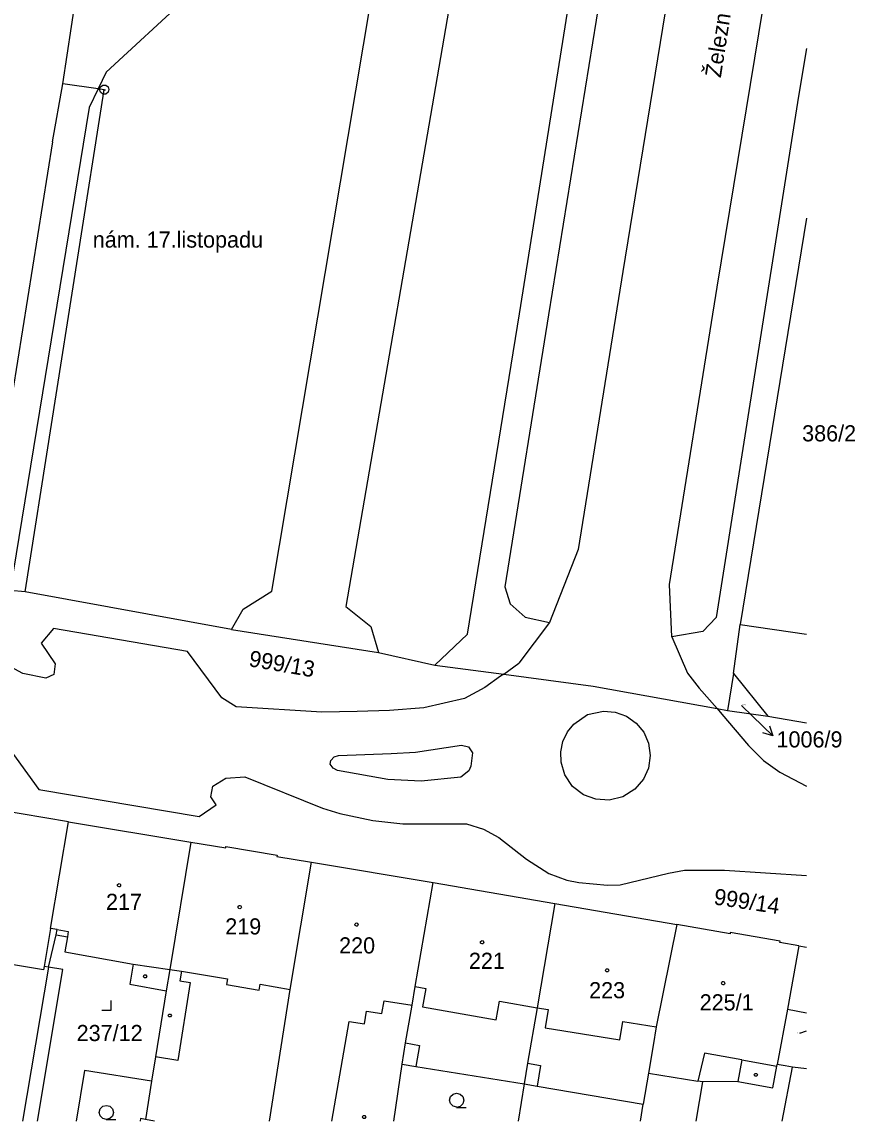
# Model space of a CAD drawing. Extents: x -851495 to -851222, y -1010479 to -1010202.
# Drawn here: x -851310.2 to -851222.4, y -1010478.7 to -1010362.9 of the extents above; entities that cross this region are included whole.
import ezdxf

# ---------------------------------------------------------------- set-up
doc = ezdxf.new("R2010")
doc.units = 0
for name, color, linetype in [('1', 7, 'Continuous'), ('12', 7, 'Continuous'), ('2', 7, 'Continuous'), ('3', 7, 'Continuous'), ('4', 7, 'Continuous'), ('5', 7, 'Continuous'), ('7', 7, 'Continuous'), ('8', 7, 'Continuous')]:
    doc.layers.add(name, color=color, linetype=linetype)

# ---------------------------------------------------------------- blocks, each defined once
blk = doc.blocks.new('304')
blk.add_lwpolyline([(0, 0), (-0.38, 0.1), (-0.65, 0.37), (-0.75, 0.74), (-0.65, 1.11), (-0.38, 1.38), (-0.01, 1.48), (0.36, 1.38), (0.63, 1.11), (0.73, 0.73), (0.63, 0.35), (0.36, 0.08), (-0.02, -0.02), (0.98, -0.02)])
blk = doc.blocks.new('319')
blk.add_lwpolyline([(-0.5, 0), (0.5, 0), (0.5, 1)])
blk = doc.blocks.new('10292')
blk.add_line((0, 3), (0, 0))
blk.add_lwpolyline([(-0.5, 2), (0, 3), (0.5, 2)])
blk = doc.blocks.new('402')
blk.add_lwpolyline([(0.09, 0.15), (0.18, 0), (0.09, -0.15), (-0.09, -0.15), (-0.18, 0), (-0.09, 0.15), (0.09, 0.15)])
blk = doc.blocks.new('105')
blk.add_line((-0.12, 0), (0.12, 0))
blk.add_lwpolyline([(0.15, 0.48), (0.4, 0.3), (0.5, 0.01), (0.4, -0.28), (0.15, -0.46), (-0.16, -0.46), (-0.41, -0.28), (-0.51, 0.01), (-0.41, 0.3), (-0.16, 0.48), (0.15, 0.48)])
blk = doc.blocks.new('404')
blk.add_lwpolyline([(0, 0.17), (0.1, 0.15), (0.15, 0.06), (0.17, 0), (0.15, -0.09), (0.07, -0.16), (0, -0.17), (-0.09, -0.14), (-0.15, -0.08), (-0.17, 0), (-0.15, 0.09), (-0.07, 0.16), (0, 0.17)])

msp = doc.modelspace()

# ---------------------------------------------------------------- linework, layer by layer
at = {"layer": '1'}
for p, q in [((-851305.87, -1010369.39), (-851303.96, -1010356.63)), ((-851242.07, -1010359.77), (-851246.84, -1010389.17)), ((-851302.16, -1010369.92), (-851305.87, -1010369.39)), ((-851301.51, -1010370.01), (-851302.16, -1010369.92)), ((-851309.84, -1010422.92), (-851301.51, -1010370.01)), ((-851227.5, -1010383.55), (-851234.48, -1010426.35)), ((-851246.84, -1010389.17), (-851251.57, -1010418.46)), ((-851251.57, -1010418.46), (-851254.57, -1010426.15)), ((-851309.84, -1010422.92), (-851311.44, -1010422.76)), ((-851288.09, -1010426.86), (-851309.84, -1010422.92)), ((-851254.57, -1010426.15), (-851257.83, -1010430.41)), ((-851235.2, -1010431.5), (-851234.48, -1010426.35)), ((-851234.48, -1010426.35), (-851227.5, -1010427.36)), ((-851306.87, -1010426.78), (-851308.15, -1010428.31)), ((-851292.74, -1010429.19), (-851306.87, -1010426.78)), ((-851288.09, -1010426.86), (-851272.59, -1010429.29)), ((-851308.15, -1010428.31), (-851306.7, -1010430.49)), ((-851289.12, -1010434.09), (-851292.74, -1010429.19)), ((-851272.59, -1010429.29), (-851266.67, -1010430.62)), ((-851310.1, -1010431.5), (-851312.57, -1010430.18)), ((-851306.7, -1010430.49), (-851306.81, -1010431.62)), ((-851266.67, -1010430.62), (-851259.39, -1010431.59)), ((-851259.39, -1010431.59), (-851257.83, -1010430.41)), ((-851307.65, -1010432), (-851310.1, -1010431.5)), ((-851306.81, -1010431.62), (-851307.65, -1010432)), ((-851259.76, -1010431.8), (-851261.39, -1010432.98)), ((-851259.39, -1010431.59), (-851259.76, -1010431.8)), ((-851259.39, -1010431.59), (-851249.99, -1010432.85)), ((-851235.2, -1010431.5), (-851235.84, -1010435.39)), ((-851235.2, -1010431.5), (-851231.57, -1010436.01)), ((-851261.39, -1010432.98), (-851263.56, -1010434.13)), ((-851249.99, -1010432.85), (-851236.92, -1010435.2)), ((-851287.62, -1010435.01), (-851289.12, -1010434.09)), ((-851263.56, -1010434.13), (-851267.84, -1010435.13)), ((-851278.59, -1010435.57), (-851287.62, -1010435.01)), ((-851274.84, -1010435.52), (-851278.59, -1010435.57)), ((-851271.44, -1010435.4), (-851274.84, -1010435.52)), ((-851267.84, -1010435.13), (-851271.44, -1010435.4)), ((-851236.92, -1010435.2), (-851235.84, -1010435.39)), ((-851236.92, -1010435.2), (-851236.41, -1010435.78)), ((-851236.41, -1010435.78), (-851233.63, -1010439.08)), ((-851235.84, -1010435.39), (-851231.57, -1010436.01)), ((-851231.57, -1010436.01), (-851227.5, -1010436.72)), ((-851311.97, -1010438.79), (-851308.42, -1010443.72)), ((-851233.63, -1010439.08), (-851232.04, -1010440.68)), ((-851232.04, -1010440.68), (-851230.3, -1010441.91)), ((-851290.08, -1010443.38), (-851288.68, -1010442.53)), ((-851288.68, -1010442.53), (-851286.71, -1010442.41)), ((-851286.71, -1010442.41), (-851278.51, -1010445.68)), ((-851230.3, -1010441.91), (-851227.5, -1010443.37)), ((-851308.42, -1010443.72), (-851291.49, -1010446.56)), ((-851290.26, -1010444.49), (-851290.08, -1010443.38)), ((-851289.7, -1010445.36), (-851290.26, -1010444.49)), ((-851305.28, -1010447.12), (-851316.57, -1010445.23)), ((-851291.49, -1010446.56), (-851289.7, -1010445.36)), ((-851278.51, -1010445.68), (-851276.67, -1010446.25)), ((-851276.67, -1010446.25), (-851273.21, -1010447)), ((-851307.18, -1010458.37), (-851305.28, -1010447.12)), ((-851305.28, -1010447.12), (-851292.38, -1010449.28)), ((-851273.21, -1010447), (-851270.04, -1010447.35)), ((-851270.04, -1010447.35), (-851263.33, -1010447.35)), ((-851263.33, -1010447.35), (-851261.53, -1010447.92)), ((-851261.53, -1010447.92), (-851259.94, -1010448.77)), ((-851292.38, -1010449.28), (-851294.6, -1010462.68)), ((-851292.38, -1010449.28), (-851288.71, -1010449.89)), ((-851288.71, -1010449.89), (-851288.69, -1010449.75)), ((-851288.69, -1010449.75), (-851283.29, -1010450.64)), ((-851259.94, -1010448.77), (-851257.01, -1010451.05)), ((-851283.29, -1010450.64), (-851283.31, -1010450.78)), ((-851283.31, -1010450.78), (-851279.68, -1010451.38)), ((-851281.9, -1010464.78), (-851279.68, -1010451.38)), ((-851279.68, -1010451.38), (-851266.85, -1010453.52)), ((-851257.01, -1010451.05), (-851254.65, -1010452.56)), ((-851254.65, -1010452.56), (-851252.75, -1010453.27)), ((-851252.75, -1010453.27), (-851251.49, -1010453.52)), ((-851247.15, -1010453.76), (-851242.06, -1010452.53)), ((-851242.06, -1010452.53), (-851240.35, -1010452.22)), ((-851240.35, -1010452.22), (-851236.13, -1010452.21)), ((-851236.13, -1010452.21), (-851227.5, -1010452.8)), ((-851268.73, -1010464.49), (-851266.85, -1010453.52)), ((-851266.85, -1010453.52), (-851254.03, -1010455.72)), ((-851251.49, -1010453.52), (-851248.46, -1010453.82)), ((-851248.46, -1010453.82), (-851247.15, -1010453.76)), ((-851254.03, -1010455.72), (-851255.89, -1010466.71)), ((-851254.03, -1010455.72), (-851241.18, -1010457.95)), ((-851307.4, -1010462.45), (-851306.56, -1010459.04)), ((-851306.46, -1010458.49), (-851307.18, -1010458.37)), ((-851306.56, -1010459.04), (-851306.46, -1010458.49)), ((-851306.46, -1010458.49), (-851305.3, -1010458.68)), ((-851305.3, -1010458.68), (-851305.4, -1010459.26)), ((-851241.18, -1010457.95), (-851243.34, -1010468.73)), ((-851235.56, -1010458.93), (-851241.18, -1010457.95)), ((-851235.53, -1010458.79), (-851235.56, -1010458.93)), ((-851230.28, -1010459.71), (-851235.53, -1010458.79)), ((-851305.4, -1010459.26), (-851305.65, -1010460.84)), ((-851230.31, -1010459.85), (-851230.28, -1010459.71)), ((-851228.3, -1010460.2), (-851230.31, -1010459.85)), ((-851228.3, -1010460.2), (-851229.52, -1010466.86)), ((-851228.3, -1010460.2), (-851227.5, -1010460.34)), ((-851307.9, -1010462.72), (-851318.74, -1010460.9)), ((-851305.65, -1010460.84), (-851298.47, -1010462.13)), ((-851307.84, -1010462.38), (-851307.9, -1010462.72)), ((-851307.4, -1010462.45), (-851307.84, -1010462.38)), ((-851305.89, -1010462.7), (-851307.4, -1010462.45)), ((-851298.47, -1010462.13), (-851298.83, -1010464.25)), ((-851308.54, -1010478.65), (-851305.89, -1010462.7)), ((-851294.6, -1010462.68), (-851294.99, -1010464.95)), ((-851298.83, -1010464.25), (-851294.99, -1010464.95)), ((-851284.09, -1010478.65), (-851281.9, -1010464.78)), ((-851269.07, -1010466.46), (-851268.73, -1010464.49)), ((-851294.99, -1010464.95), (-851296.11, -1010471.88)), ((-851269.75, -1010470.43), (-851269.07, -1010466.46)), ((-851255.89, -1010466.71), (-851256.92, -1010472.57)), ((-851229.52, -1010466.86), (-851230.6, -1010472.71)), ((-851229.52, -1010466.86), (-851227.5, -1010467.27)), ((-851243.34, -1010468.73), (-851243.67, -1010470.7)), ((-851270.13, -1010472.65), (-851269.75, -1010470.43)), ((-851243.67, -1010470.7), (-851244.16, -1010473.61)), ((-851296.11, -1010471.88), (-851296.53, -1010474.46)), ((-851271, -1010478.65), (-851270.13, -1010472.65)), ((-851270.13, -1010472.65), (-851268.67, -1010472.9)), ((-851268.67, -1010472.9), (-851257.27, -1010474.75)), ((-851256.92, -1010472.57), (-851257.27, -1010474.75)), ((-851231.06, -1010475.17), (-851230.63, -1010472.86)), ((-851230.63, -1010472.86), (-851230.6, -1010472.71)), ((-851229.75, -1010472.85), (-851230.6, -1010472.71)), ((-851230.05, -1010478.65), (-851228.97, -1010472.96)), ((-851228.97, -1010472.96), (-851229.75, -1010472.85)), ((-851227.5, -1010473.17), (-851228.97, -1010472.96)), ((-851303.59, -1010473.33), (-851304.48, -1010478.65)), ((-851296.53, -1010474.46), (-851303.59, -1010473.33)), ((-851244.16, -1010473.61), (-851244.71, -1010476.86)), ((-851244.16, -1010473.61), (-851238.94, -1010474.45)), ((-851296.53, -1010474.46), (-851297.18, -1010478.48)), ((-851257.27, -1010474.75), (-851257.87, -1010478.65)), ((-851257.27, -1010474.75), (-851255.87, -1010474.97)), ((-851255.87, -1010474.97), (-851244.71, -1010476.86)), ((-851238.45, -1010474.53), (-851239.15, -1010478.65)), ((-851238.45, -1010474.53), (-851238.94, -1010474.45)), ((-851234.73, -1010474.48), (-851238.45, -1010474.53)), ((-851234.73, -1010474.48), (-851231.06, -1010475.17)), ((-851245.01, -1010478.65), (-851244.71, -1010476.86)), ((-851297.68, -1010478.39), (-851297.73, -1010478.65)), ((-851297.18, -1010478.48), (-851297.68, -1010478.39)), ((-851296.23, -1010478.65), (-851297.18, -1010478.48))]:
    msp.add_line(p, q, dxfattribs=at)
at = {"layer": '12'}
for p, q in [((-851227.5, -1010383.55), (-851234.48, -1010426.35)), ((-851234.48, -1010426.35), (-851227.5, -1010427.36)), ((-851305.28, -1010447.12), (-851316.57, -1010445.23)), ((-851307.18, -1010458.37), (-851305.28, -1010447.12)), ((-851307.18, -1010458.37), (-851305.28, -1010447.12)), ((-851305.28, -1010447.12), (-851292.38, -1010449.28)), ((-851292.38, -1010449.28), (-851294.6, -1010462.68)), ((-851292.38, -1010449.28), (-851294.6, -1010462.68)), ((-851292.38, -1010449.28), (-851288.71, -1010449.89)), ((-851288.71, -1010449.89), (-851288.69, -1010449.75)), ((-851288.69, -1010449.75), (-851283.29, -1010450.64)), ((-851283.29, -1010450.64), (-851283.31, -1010450.78)), ((-851283.31, -1010450.78), (-851279.68, -1010451.38)), ((-851281.9, -1010464.78), (-851279.68, -1010451.38)), ((-851281.9, -1010464.78), (-851279.68, -1010451.38)), ((-851279.68, -1010451.38), (-851266.85, -1010453.52)), ((-851268.73, -1010464.49), (-851266.85, -1010453.52)), ((-851268.73, -1010464.49), (-851266.85, -1010453.52)), ((-851266.85, -1010453.52), (-851254.03, -1010455.72)), ((-851254.03, -1010455.72), (-851255.89, -1010466.71)), ((-851254.03, -1010455.72), (-851255.89, -1010466.71)), ((-851254.03, -1010455.72), (-851241.18, -1010457.95)), ((-851307.18, -1010458.37), (-851307.84, -1010462.38)), ((-851306.46, -1010458.49), (-851307.18, -1010458.37)), ((-851306.46, -1010458.49), (-851305.3, -1010458.68)), ((-851305.3, -1010458.68), (-851305.4, -1010459.26)), ((-851241.18, -1010457.95), (-851243.34, -1010468.73)), ((-851241.18, -1010457.95), (-851243.34, -1010468.73)), ((-851235.56, -1010458.93), (-851241.18, -1010457.95)), ((-851235.53, -1010458.79), (-851235.56, -1010458.93)), ((-851230.28, -1010459.71), (-851235.53, -1010458.79)), ((-851305.4, -1010459.26), (-851305.65, -1010460.84)), ((-851230.31, -1010459.85), (-851230.28, -1010459.71)), ((-851228.3, -1010460.2), (-851230.31, -1010459.85)), ((-851228.3, -1010460.2), (-851229.52, -1010466.86)), ((-851305.65, -1010460.84), (-851298.47, -1010462.13)), ((-851307.4, -1010462.45), (-851310.11, -1010478.65)), ((-851307.4, -1010462.45), (-851307.84, -1010462.38)), ((-851298.47, -1010462.13), (-851294.6, -1010462.68)), ((-851294.6, -1010462.68), (-851293.37, -1010462.88)), ((-851293.37, -1010462.88), (-851288.53, -1010463.68)), ((-851288.53, -1010463.68), (-851288.63, -1010464.28)), ((-851288.63, -1010464.28), (-851285.19, -1010464.85)), ((-851285.19, -1010464.85), (-851285.09, -1010464.25)), ((-851285.09, -1010464.25), (-851281.9, -1010464.78)), ((-851284.09, -1010478.65), (-851281.9, -1010464.78)), ((-851269.07, -1010466.46), (-851268.73, -1010464.49)), ((-851268.73, -1010464.49), (-851267.63, -1010464.68)), ((-851267.63, -1010464.68), (-851267.96, -1010466.63)), ((-851272.24, -1010467.34), (-851272.02, -1010465.99)), ((-851272.02, -1010465.99), (-851269.07, -1010466.46)), ((-851274.08, -1010468.42), (-851273.87, -1010467.08)), ((-851273.87, -1010467.08), (-851272.24, -1010467.34)), ((-851267.96, -1010466.63), (-851260.19, -1010467.98)), ((-851260.19, -1010467.98), (-851259.85, -1010466.03)), ((-851259.85, -1010466.03), (-851255.89, -1010466.71)), ((-851255.89, -1010466.71), (-851254.73, -1010466.9)), ((-851254.73, -1010466.9), (-851255.05, -1010468.83)), ((-851229.52, -1010466.86), (-851230.6, -1010472.71)), ((-851277.51, -1010478.65), (-851275.69, -1010468.17)), ((-851275.69, -1010468.17), (-851274.08, -1010468.42)), ((-851247.16, -1010470.1), (-851246.85, -1010468.17)), ((-851246.85, -1010468.17), (-851243.34, -1010468.73)), ((-851255.05, -1010468.83), (-851247.16, -1010470.1)), ((-851243.34, -1010468.73), (-851243.67, -1010470.7)), ((-851243.67, -1010470.7), (-851244.16, -1010473.61)), ((-851238.24, -1010471.49), (-851238.94, -1010474.45)), ((-851234.3, -1010472.2), (-851238.24, -1010471.49)), ((-851234.3, -1010472.2), (-851230.63, -1010472.86)), ((-851230.63, -1010472.86), (-851230.6, -1010472.71)), ((-851244.16, -1010473.61), (-851244.71, -1010476.86)), ((-851244.16, -1010473.61), (-851238.94, -1010474.45)), ((-851244.16, -1010473.61), (-851238.94, -1010474.45)), ((-851238.45, -1010474.53), (-851239.15, -1010478.65)), ((-851238.45, -1010474.53), (-851238.94, -1010474.45)), ((-851245.01, -1010478.65), (-851244.71, -1010476.86)), ((-851297.68, -1010478.39), (-851297.73, -1010478.65)), ((-851297.18, -1010478.48), (-851297.68, -1010478.39)), ((-851296.23, -1010478.65), (-851297.18, -1010478.48))]:
    msp.add_line(p, q, dxfattribs=at)
at = {"layer": '4'}
for p, q in [((-851247.42, -1010348.78), (-851254.68, -1010393.74)), ((-851257.76, -1010393.63), (-851252.25, -1010359.13)), ((-851301.31, -1010368.16), (-851292.42, -1010359.97)), ((-851283.86, -1010422.84), (-851273.38, -1010360.47)), ((-851265.21, -1010361.53), (-851276.04, -1010424.45)), ((-851236.92, -1010390.82), (-851232.08, -1010361.34)), ((-851227.5, -1010365.69), (-851228.33, -1010370.71)), ((-851301.31, -1010368.16), (-851302.16, -1010369.92)), ((-851306.95, -1010375.51), (-851305.87, -1010369.39)), ((-851302.16, -1010369.92), (-851303.11, -1010371.88)), ((-851228.33, -1010370.71), (-851230.25, -1010382.72)), ((-851303.11, -1010371.88), (-851311.44, -1010422.76)), ((-851306.95, -1010375.51), (-851314.37, -1010421.74)), ((-851230.25, -1010382.72), (-851234.43, -1010409.16)), ((-851241.94, -1010422.12), (-851236.92, -1010390.82)), ((-851263.22, -1010427.36), (-851257.76, -1010393.63)), ((-851254.68, -1010393.74), (-851259.31, -1010422.38)), ((-851234.43, -1010409.16), (-851237.02, -1010425.6)), ((-851286.87, -1010424.73), (-851283.86, -1010422.84)), ((-851259.31, -1010422.38), (-851258.73, -1010424.17)), ((-851241.68, -1010427.66), (-851241.94, -1010422.12)), ((-851258.73, -1010424.17), (-851257.15, -1010425.59)), ((-851288.09, -1010426.86), (-851286.87, -1010424.73)), ((-851276.04, -1010424.45), (-851273.42, -1010426.56)), ((-851273.42, -1010426.56), (-851272.59, -1010429.29)), ((-851257.15, -1010425.59), (-851254.57, -1010426.15)), ((-851237.02, -1010425.6), (-851238.44, -1010427.07)), ((-851266.67, -1010430.62), (-851263.22, -1010427.36)), ((-851238.44, -1010427.07), (-851241.68, -1010427.66)), ((-851241.68, -1010427.66), (-851240.03, -1010431.49)), ((-851240.03, -1010431.49), (-851238.81, -1010433.05)), ((-851238.81, -1010433.05), (-851236.92, -1010435.2)), ((-851252.01, -1010436.83), (-851250.59, -1010435.83)), ((-851250.59, -1010435.83), (-851248.88, -1010435.48)), ((-851248.88, -1010435.48), (-851247.66, -1010435.58)), ((-851247.66, -1010435.58), (-851246.47, -1010436.01)), ((-851252.69, -1010437.67), (-851252.01, -1010436.83)), ((-851246.47, -1010436.01), (-851245.44, -1010436.74)), ((-851245.44, -1010436.74), (-851244.66, -1010437.68)), ((-851253.17, -1010438.67), (-851252.69, -1010437.67)), ((-851244.66, -1010437.68), (-851244.14, -1010438.85)), ((-851268.72, -1010439.79), (-851263.85, -1010439.05)), ((-851263.85, -1010439.05), (-851263.12, -1010439.23)), ((-851263.12, -1010439.23), (-851262.7, -1010439.87)), ((-851253.39, -1010439.77), (-851253.17, -1010438.67)), ((-851244.14, -1010438.85), (-851243.96, -1010440.16)), ((-851277.62, -1010440.66), (-851277.29, -1010440.29)), ((-851277.29, -1010440.29), (-851276.81, -1010440.14)), ((-851276.81, -1010440.14), (-851271.27, -1010439.92)), ((-851271.27, -1010439.92), (-851268.72, -1010439.79)), ((-851262.7, -1010439.87), (-851262.86, -1010441.28)), ((-851253.36, -1010440.85), (-851253.39, -1010439.77)), ((-851243.96, -1010440.16), (-851244.15, -1010441.47)), ((-851277.71, -1010441.06), (-851277.62, -1010440.66)), ((-851277.38, -1010441.47), (-851277.71, -1010441.06)), ((-851276.92, -1010441.71), (-851277.38, -1010441.47)), ((-851271.61, -1010442.66), (-851276.92, -1010441.71)), ((-851262.86, -1010441.28), (-851263.07, -1010441.76)), ((-851252.98, -1010442.19), (-851253.36, -1010440.85)), ((-851244.15, -1010441.47), (-851244.68, -1010442.64)), ((-851268.12, -1010442.85), (-851271.61, -1010442.66)), ((-851263.94, -1010442.42), (-851268.12, -1010442.85)), ((-851263.07, -1010441.76), (-851263.94, -1010442.42)), ((-851252.17, -1010443.4), (-851252.98, -1010442.19)), ((-851244.68, -1010442.64), (-851245.6, -1010443.71)), ((-851251.01, -1010444.28), (-851252.17, -1010443.4)), ((-851245.6, -1010443.71), (-851246.86, -1010444.5)), ((-851249.71, -1010444.75), (-851251.01, -1010444.28)), ((-851248.3, -1010444.85), (-851249.71, -1010444.75)), ((-851246.86, -1010444.5), (-851248.3, -1010444.85)), ((-851307.18, -1010458.37), (-851307.84, -1010462.38)), ((-851306.56, -1010459.04), (-851305.4, -1010459.26)), ((-851307.4, -1010462.45), (-851310.11, -1010478.65)), ((-851298.47, -1010462.13), (-851294.6, -1010462.68)), ((-851294.6, -1010462.68), (-851293.37, -1010462.88)), ((-851293.37, -1010462.88), (-851293.53, -1010463.87)), ((-851293.37, -1010462.88), (-851288.53, -1010463.68)), ((-851288.53, -1010463.68), (-851288.63, -1010464.28)), ((-851292.44, -1010464.05), (-851293.77, -1010472.28)), ((-851293.53, -1010463.87), (-851292.44, -1010464.05)), ((-851288.63, -1010464.28), (-851285.19, -1010464.85)), ((-851285.19, -1010464.85), (-851285.09, -1010464.25)), ((-851285.09, -1010464.25), (-851281.9, -1010464.78)), ((-851268.73, -1010464.49), (-851267.63, -1010464.68)), ((-851267.63, -1010464.68), (-851267.96, -1010466.63)), ((-851272.24, -1010467.34), (-851272.02, -1010465.99)), ((-851272.02, -1010465.99), (-851269.07, -1010466.46)), ((-851274.08, -1010468.42), (-851273.87, -1010467.08)), ((-851273.87, -1010467.08), (-851272.24, -1010467.34)), ((-851267.96, -1010466.63), (-851260.19, -1010467.98)), ((-851260.19, -1010467.98), (-851259.85, -1010466.03)), ((-851259.85, -1010466.03), (-851255.89, -1010466.71)), ((-851255.89, -1010466.71), (-851254.73, -1010466.9)), ((-851254.73, -1010466.9), (-851255.05, -1010468.83)), ((-851277.51, -1010478.65), (-851275.69, -1010468.17)), ((-851275.69, -1010468.17), (-851274.08, -1010468.42)), ((-851247.16, -1010470.1), (-851246.85, -1010468.17)), ((-851246.85, -1010468.17), (-851243.34, -1010468.73)), ((-851255.05, -1010468.83), (-851247.16, -1010470.1)), ((-851269.75, -1010470.43), (-851268.29, -1010470.68)), ((-851268.29, -1010470.68), (-851268.67, -1010472.9)), ((-851238.24, -1010471.49), (-851238.94, -1010474.45)), ((-851234.3, -1010472.2), (-851238.24, -1010471.49)), ((-851293.77, -1010472.28), (-851296.11, -1010471.88)), ((-851256.92, -1010472.57), (-851255.52, -1010472.79)), ((-851255.52, -1010472.79), (-851255.87, -1010474.97)), ((-851234.3, -1010472.2), (-851234.73, -1010474.48)), ((-851234.3, -1010472.2), (-851230.63, -1010472.86))]:
    msp.add_line(p, q, dxfattribs=at)
at = {"layer": '7'}
for p, q in [((-851234.36, -1010434.87), (-851233.19, -1010436)), ((-851228.22, -1010469.41), (-851227.5, -1010469.15))]:
    msp.add_line(p, q, dxfattribs=at)

# ---------------------------------------------------------------- block references
at = {"layer": '3'}
for name, p in [('319', (-851301.27, -1010466.97)), ('304', (-851264.36, -1010477.19)), ('304', (-851301.28, -1010478.48))]:
    msp.add_blockref(name, p, dxfattribs=at)
at = {"layer": '5'}
for name, p in [('404', (-851299.95, -1010453.81)), ('404', (-851287.23, -1010456.12)), ('404', (-851274.92, -1010457.96)), ('404', (-851261.69, -1010459.82)), ('402', (-851297.21, -1010463.41)), ('404', (-851248.51, -1010462.78)), ('404', (-851236.29, -1010464.13)), ('402', (-851294.61, -1010467.53)), ('402', (-851232.84, -1010473.78)), ('402', (-851274.12, -1010478.22))]:
    msp.add_blockref(name, p, dxfattribs=at)
at = {"layer": '7', "rotation": -134.02544599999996}
msp.add_blockref('10292', (-851233.19, -1010436), dxfattribs=at)
at = {"layer": '8'}
msp.add_blockref('105', (-851301.51, -1010370.01), dxfattribs=at)

# ---------------------------------------------------------------- texts
at = {"layer": '2'}
for s, height, p in [('386/2', 1.7, (-851227.96, -1010407.06)), ('1006/9', 0.1, (-851234.34, -1010434.87)), ('217', 1.7, (-851301.33, -1010456.41)), ('219', 1.7, (-851288.76, -1010459)), ('220', 1.7, (-851276.76, -1010461)), ('221', 1.7, (-851263.08, -1010462.62)), ('223', 1.7, (-851250.41, -1010465.72)), ('225/1', 1.7, (-851238.76, -1010467)), ('237/12', 1.7, (-851304.42, -1010470.23)), ('225/6', 0.1, (-851228.46, -1010469.41))]:
    msp.add_text(s, height=height, dxfattribs=at).set_placement(p)
for s, rotation, p in [('999/13', 350.135, (-851286.35, -1010430.73)), ('999/14', 351.395, (-851237.34, -1010455.82))]:
    msp.add_text(s, height=1.7, rotation=rotation, dxfattribs=at).set_placement(p)
at = {"layer": '7'}
msp.add_text('Železniční', height=1.7, rotation=81.131, dxfattribs=at).set_placement((-851236.53, -1010368.81))
for s, p in [('nám. 17.listopadu', (-851302.72, -1010386.65)), ('1006/9', (-851230.66, -1010439.3))]:
    msp.add_text(s, height=1.7, dxfattribs=at).set_placement(p)

doc.saveas('drawing.dxf')
